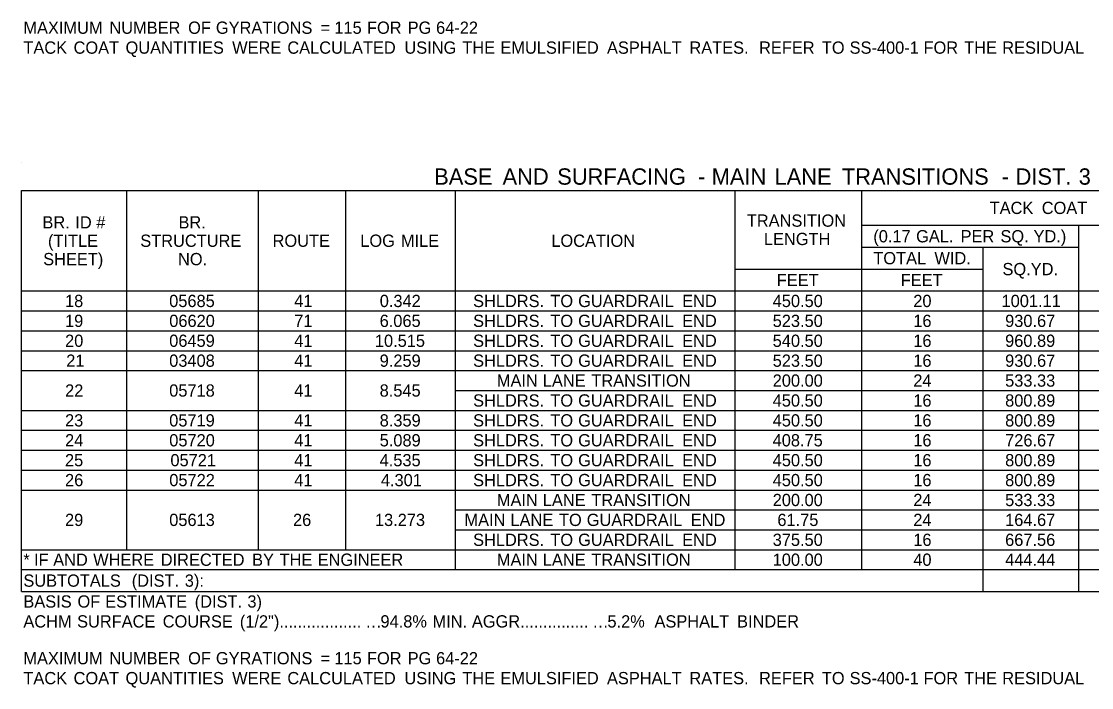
# Model space of a CAD drawing. Extents: x 544250 to 1930787, y -1948365 to 596640.
# Drawn here: x 552201 to 552725, y -1946877 to -1946551 of the extents above; entities that cross this region are included whole.
import ezdxf

# ---------------------------------------------------------------- set-up
doc = ezdxf.new("R2010")
doc.units = 0
doc.layers.add('Default', color=7, linetype='Continuous')

msp = doc.modelspace()

# ---------------------------------------------------------------- linework, layer by layer
at = {"layer": 'Default'}
for p, q in [((552201.23, -1946619.99), (552201.23, -1946619.99)), ((552201.23, -1946633.64), (552997.32, -1946633.64)), ((552201.23, -1946830.1), (552201.23, -1946633.64)), ((552252.9, -1946682.87), (552252.9, -1946633.64)), ((552317.25, -1946682.87), (552317.25, -1946633.64)), ((552360.15, -1946682.87), (552360.15, -1946633.64)), ((552413.78, -1946819.37), (552413.78, -1946633.64)), ((552550.77, -1946819.37), (552550.77, -1946633.64)), ((552612.68, -1946819.37), (552612.68, -1946633.64)), ((552612.68, -1946650.7), (552612.68, -1946633.64)), ((552612.68, -1946650.7), (552997.32, -1946650.7)), ((552718.95, -1946661.42), (552718.95, -1946650.7)), ((552718.95, -1946830.1), (552718.95, -1946650.7)), ((552612.68, -1946661.42), (552718.95, -1946661.42)), ((552672.15, -1946830.1), (552672.15, -1946661.42)), ((552550.77, -1946672.15), (552612.68, -1946672.15)), ((552550.77, -1946672.15), (552672.15, -1946672.15)), ((552672.15, -1946682.87), (552672.15, -1946672.15)), ((552201.23, -1946682.87), (552672.15, -1946682.87)), ((552252.9, -1946809.62), (552252.9, -1946682.87)), ((552317.25, -1946809.62), (552317.25, -1946682.87)), ((552360.15, -1946809.62), (552360.15, -1946682.87)), ((552672.15, -1946682.87), (552838.88, -1946682.87)), ((552672.15, -1946682.87), (552718.95, -1946682.87)), ((552201.23, -1946692.62), (552997.32, -1946692.62)), ((552201.23, -1946692.62), (552997.32, -1946692.62)), ((552201.23, -1946702.37), (552997.32, -1946702.37)), ((552201.23, -1946702.37), (552997.32, -1946702.37)), ((552201.23, -1946712.12), (552997.32, -1946712.12)), ((552201.23, -1946712.12), (552997.32, -1946712.12)), ((552201.23, -1946721.87), (552997.32, -1946721.87)), ((552413.78, -1946721.87), (552997.32, -1946721.87)), ((552413.78, -1946731.62), (552997.32, -1946731.62)), ((552413.78, -1946731.62), (552997.32, -1946731.62)), ((552201.23, -1946741.37), (552997.32, -1946741.37)), ((552201.23, -1946741.37), (552997.32, -1946741.37)), ((552201.23, -1946751.12), (552997.32, -1946751.12)), ((552201.23, -1946751.12), (552997.32, -1946751.12)), ((552201.23, -1946760.87), (552997.32, -1946760.87)), ((552201.23, -1946760.87), (552997.32, -1946760.87)), ((552201.23, -1946770.62), (552997.32, -1946770.62)), ((552201.23, -1946770.62), (552997.32, -1946770.62)), ((552201.23, -1946780.37), (552997.32, -1946780.37)), ((552201.23, -1946780.37), (552413.78, -1946780.37)), ((552413.78, -1946780.37), (552997.32, -1946780.37)), ((552413.78, -1946790.12), (552997.32, -1946790.12)), ((552413.78, -1946799.87), (552550.77, -1946799.87)), ((552413.78, -1946799.87), (552997.32, -1946799.87)), ((552672.15, -1946799.87), (552997.32, -1946799.87)), ((552201.23, -1946809.62), (552997.32, -1946809.62)), ((552413.78, -1946809.62), (552997.32, -1946809.62)), ((552201.23, -1946819.37), (552997.32, -1946819.37)), ((552201.23, -1946830.1), (552997.32, -1946830.1))]:
    msp.add_line(p, q, dxfattribs=at)

# ---------------------------------------------------------------- texts
for s, height, p in [('MAXIMUM', 6, (552202.2, -1946556.9)), (' NUMBER', 6, (552242.09, -1946556.9)), (' OF', 6, (552280.64, -1946556.9)), (' GYRATIONS', 6, (552294.23, -1946556.9)), (' =', 6, (552345.5, -1946556.9)), (' 115', 6, (552352.25, -1946556.9)), (' FOR', 6, (552368.22, -1946556.9)), (' PG', 6, (552388.14, -1946556.9)), (' 64-22', 6, (552402.05, -1946556.9)), ('TACK', 6, (552202.2, -1946566.65)), (' COAT', 6, (552224.55, -1946566.65)), (' QUANTITIES', 6, (552250, -1946566.65)), (' WERE', 6, (552302.2, -1946566.65)), (' CALCULATED', 6, (552329.23, -1946566.65)), (' USING', 6, (552386.55, -1946566.65)), (' THE', 6, (552414.9, -1946566.65)), (' EMULSIFIED', 6, (552433.55, -1946566.65)), (' ASPHALT', 6, (552485.74, -1946566.65)), (' RATES.', 6, (552526.11, -1946566.65)), ('  REFER', 6, (552557.99, -1946566.65)), (' TO', 6, (552590.95, -1946566.65)), (' SS-400-1', 6, (552604.54, -1946566.65)), (' FOR', 6, (552640.74, -1946566.65)), (' THE', 6, (552660.65, -1946566.65)), (' RESIDUAL', 6, (552679.3, -1946566.65)), ('BASE', 8, (552403.37, -1946630.81)), (' AND', 8, (552433.87, -1946630.81)), (' SURFACING', 8, (552460.64, -1946630.81)), (' -', 8, (552529.52, -1946630.81)), (' MAIN', 8, (552536.26, -1946630.81)), (' LANE', 8, (552567.03, -1946630.81)), (' TRANSITIONS', 8, (552600.01, -1946630.81)), (' -', 8, (552678.34, -1946630.81)), (' DIST.', 8, (552685.08, -1946630.81)), (' 3', 8, (552715.98, -1946630.81)), ('TACK', 6, (552675.35, -1946645.17)), (' COAT', 6, (552698.63, -1946645.17)), ('BR.', 6, (552211.54, -1946652.25)), (' ID', 6, (552225.4, -1946652.25)), (' #', 6, (552235.7, -1946652.25)), ('BR.', 6, (552278.15, -1946652.25)), ('TRANSITION', 6, (552556.44, -1946651.39)), ('(0.17', 6, (552618.38, -1946659.06)), (' GAL.', 6, (552637.1, -1946659.06)), (' PER', 6, (552658.88, -1946659.06)), (' SQ.', 6, (552678.41, -1946659.06)), (' YD.)', 6, (552694.6, -1946659.06)), ('(TITLE', 6, (552214.24, -1946661.25)), ('STRUCTURE', 6, (552259.44, -1946661.25)), ('ROUTE', 6, (552324.24, -1946661.25)), ('LOG', 6, (552367.17, -1946661.25)), (' MILE', 6, (552384.83, -1946661.25)), ('LOCATION', 6, (552460.72, -1946661.25)), ('LENGTH', 6, (552564.81, -1946660.39)), ('SHEET)', 6, (552211.91, -1946670.25)), ('NO.', 6, (552277.92, -1946670.25)), ('TOTAL', 6, (552618.39, -1946669.79)), (' WID.', 6, (552646.08, -1946669.79)), ('SQ.YD.', 6, (552681.63, -1946675.15)), ('FEET', 6, (552571.1, -1946680.51)), ('FEET', 6, (552631.79, -1946680.51)), ('18', 6, (552222.59, -1946690.75)), ('05685', 6, (552273.6, -1946690.75)), ('41', 6, (552334.82, -1946690.75)), ('0.342', 6, (552376.7, -1946690.75)), ('SHLDRS.', 6, (552422.41, -1946690.75)), (' TO', 6, (552458.01, -1946690.75)), (' GUARDRAIL', 6, (552471.61, -1946690.75)), (' END', 6, (552522.56, -1946690.75)), ('450.50', 6, (552569.11, -1946690.75)), ('20', 6, (552637.96, -1946690.75)), ('1001.11', 6, (552681.18, -1946690.75)), ('19', 6, (552222.59, -1946700.5)), ('06620', 6, (552273.63, -1946700.5)), ('71', 6, (552334.82, -1946700.5)), ('6.065', 6, (552376.65, -1946700.5)), ('SHLDRS.', 6, (552422.41, -1946700.5)), (' TO', 6, (552458.01, -1946700.5)), (' GUARDRAIL', 6, (552471.61, -1946700.5)), (' END', 6, (552522.56, -1946700.5)), ('523.50', 6, (552569.11, -1946700.5)), ('16', 6, (552637.95, -1946700.5)), ('930.67', 6, (552682.93, -1946700.5)), ('20', 6, (552222.61, -1946710.25)), ('06459', 6, (552273.61, -1946710.25)), ('41', 6, (552334.82, -1946710.25)), ('10.515', 6, (552374.32, -1946710.25)), ('SHLDRS.', 6, (552422.41, -1946710.25)), (' TO', 6, (552458.01, -1946710.25)), (' GUARDRAIL', 6, (552471.61, -1946710.25)), (' END', 6, (552522.56, -1946710.25)), ('540.50', 6, (552569.11, -1946710.25)), ('16', 6, (552637.95, -1946710.25)), ('960.89', 6, (552682.93, -1946710.25)), ('21', 6, (552223.18, -1946720)), ('03408', 6, (552273.61, -1946720)), ('41', 6, (552334.82, -1946720)), ('9.259', 6, (552376.67, -1946720)), ('SHLDRS.', 6, (552422.41, -1946720)), (' TO', 6, (552458.01, -1946720)), (' GUARDRAIL', 6, (552471.61, -1946720)), (' END', 6, (552522.56, -1946720)), ('523.50', 6, (552569.11, -1946720)), ('16', 6, (552637.95, -1946720)), ('930.67', 6, (552682.93, -1946720)), ('MAIN', 6, (552434.04, -1946729.75)), (' LANE', 6, (552454.31, -1946729.75)), (' TRANSITION', 6, (552478.09, -1946729.75)), ('200.00', 6, (552569.11, -1946729.75)), ('24', 6, (552637.96, -1946729.75)), ('533.33', 6, (552682.93, -1946729.75)), ('22', 6, (552222.63, -1946734.62)), ('05718', 6, (552273.61, -1946734.62)), ('41', 6, (552334.82, -1946734.62)), ('8.545', 6, (552376.65, -1946734.62)), ('SHLDRS.', 6, (552422.41, -1946739.5)), (' TO', 6, (552458.01, -1946739.5)), (' GUARDRAIL', 6, (552471.61, -1946739.5)), (' END', 6, (552522.56, -1946739.5)), ('450.50', 6, (552569.11, -1946739.5)), ('16', 6, (552637.95, -1946739.5)), ('800.89', 6, (552682.93, -1946739.5)), ('23', 6, (552222.6, -1946749.25)), ('05719', 6, (552273.61, -1946749.25)), ('41', 6, (552334.82, -1946749.25)), ('8.359', 6, (552376.67, -1946749.25)), ('SHLDRS.', 6, (552422.41, -1946749.25)), (' TO', 6, (552458.01, -1946749.25)), (' GUARDRAIL', 6, (552471.61, -1946749.25)), (' END', 6, (552522.56, -1946749.25)), ('450.50', 6, (552569.11, -1946749.25)), ('16', 6, (552637.95, -1946749.25)), ('800.89', 6, (552682.93, -1946749.25)), ('24', 6, (552222.61, -1946759)), ('05720', 6, (552273.63, -1946759)), ('41', 6, (552334.82, -1946759)), ('5.089', 6, (552376.67, -1946759)), ('SHLDRS.', 6, (552422.41, -1946759)), (' TO', 6, (552458.01, -1946759)), (' GUARDRAIL', 6, (552471.61, -1946759)), (' END', 6, (552522.56, -1946759)), ('408.75', 6, (552569.08, -1946759)), ('16', 6, (552637.95, -1946759)), ('726.67', 6, (552682.93, -1946759)), ('25', 6, (552222.57, -1946768.75)), ('05721', 6, (552274.2, -1946768.75)), ('41', 6, (552334.82, -1946768.75)), ('4.535', 6, (552376.65, -1946768.75)), ('SHLDRS.', 6, (552422.41, -1946768.75)), (' TO', 6, (552458.01, -1946768.75)), (' GUARDRAIL', 6, (552471.61, -1946768.75)), (' END', 6, (552522.56, -1946768.75)), ('450.50', 6, (552569.11, -1946768.75)), ('16', 6, (552637.95, -1946768.75)), ('800.89', 6, (552682.93, -1946768.75)), ('26', 6, (552222.6, -1946778.5)), ('05722', 6, (552273.65, -1946778.5)), ('41', 6, (552334.82, -1946778.5)), ('4.301', 6, (552377.25, -1946778.5)), ('SHLDRS.', 6, (552422.41, -1946778.5)), (' TO', 6, (552458.01, -1946778.5)), (' GUARDRAIL', 6, (552471.61, -1946778.5)), (' END', 6, (552522.56, -1946778.5)), ('450.50', 6, (552569.11, -1946778.5)), ('16', 6, (552637.95, -1946778.5)), ('800.89', 6, (552682.93, -1946778.5)), ('MAIN', 6, (552434.04, -1946788.25)), (' LANE', 6, (552454.31, -1946788.25)), (' TRANSITION', 6, (552478.09, -1946788.25)), ('200.00', 6, (552569.11, -1946788.25)), ('24', 6, (552637.96, -1946788.25)), ('533.33', 6, (552682.93, -1946788.25)), ('29', 6, (552222.59, -1946798)), ('05613', 6, (552273.62, -1946798)), ('26', 6, (552334.23, -1946798)), ('13.273', 6, (552374.34, -1946798)), ('MAIN', 6, (552418.18, -1946798)), (' LANE', 6, (552438.46, -1946798)), (' TO', 6, (552462.24, -1946798)), (' GUARDRAIL', 6, (552475.83, -1946798)), (' END', 6, (552526.78, -1946798)), ('61.75', 6, (552571.41, -1946798)), ('24', 6, (552637.96, -1946798)), ('164.67', 6, (552682.93, -1946798)), ('SHLDRS.', 6, (552422.41, -1946807.75)), (' TO', 6, (552458.01, -1946807.75)), (' GUARDRAIL', 6, (552471.61, -1946807.75)), (' END', 6, (552522.56, -1946807.75)), ('375.50', 6, (552569.11, -1946807.75)), ('16', 6, (552637.95, -1946807.75)), ('667.56', 6, (552682.93, -1946807.75)), ('*', 6, (552202.2, -1946817.5)), (' IF', 6, (552205.17, -1946817.5)), (' AND', 6, (552214.57, -1946817.5)), (' WHERE', 6, (552234.15, -1946817.5)), (' DIRECTED', 6, (552267.24, -1946817.5)), (' BY', 6, (552311.97, -1946817.5)), (' THE', 6, (552325.42, -1946817.5)), (' ENGINEER', 6, (552344.07, -1946817.5)), ('MAIN', 6, (552434.04, -1946817.5)), (' LANE', 6, (552454.31, -1946817.5)), (' TRANSITION', 6, (552478.09, -1946817.5)), ('100.00', 6, (552569.11, -1946817.5)), ('40', 6, (552637.96, -1946817.5)), ('444.44', 6, (552682.94, -1946817.5)), ('SUBTOTALS', 6, (552202.2, -1946827.74)), (' (DIST.', 6, (552253.03, -1946827.74)), (' 3):', 6, (552279, -1946827.74)), ('BASIS', 6, (552202.2, -1946837.97)), (' OF', 6, (552226.47, -1946837.97)), (' ESTIMATE', 6, (552240.05, -1946837.97)), (' (DIST.', 6, (552283.86, -1946837.97)), (' 3)', 6, (552309.67, -1946837.97)), ('ACHM', 6, (552202.2, -1946847.72)), (' SURFACE', 6, (552226.26, -1946847.72)), (' COURSE', 6, (552268.2, -1946847.72)), (' (1/2")..................', 6, (552305.96, -1946847.72)), ('94.8%', 6, (552377.06, -1946847.72)), (' MIN.', 6, (552400.3, -1946847.72)), (' AGGR...............', 6, (552419.59, -1946847.72)), ('5.2%', 6, (552488.19, -1946847.72)), ('  ASPHALT', 6, (552506.77, -1946847.72)), (' BINDER', 6, (552549.46, -1946847.72)), ('…', 6, (552369.66, -1946847.72)), ('…', 6, (552480.79, -1946847.72)), ('MAXIMUM', 6, (552202.2, -1946865.76)), (' NUMBER', 6, (552242.09, -1946865.76)), (' OF', 6, (552280.64, -1946865.76)), (' GYRATIONS', 6, (552294.23, -1946865.76)), (' =', 6, (552345.5, -1946865.76)), (' 115', 6, (552352.25, -1946865.76)), (' FOR', 6, (552368.22, -1946865.76)), (' PG', 6, (552388.14, -1946865.76)), (' 64-22', 6, (552402.05, -1946865.76)), ('TACK', 6, (552202.2, -1946875.51)), (' COAT', 6, (552224.55, -1946875.51)), (' QUANTITIES', 6, (552250, -1946875.51)), (' WERE', 6, (552302.2, -1946875.51)), (' CALCULATED', 6, (552329.23, -1946875.51)), (' USING', 6, (552386.55, -1946875.51)), (' THE', 6, (552414.9, -1946875.51)), (' EMULSIFIED', 6, (552433.55, -1946875.51)), (' ASPHALT', 6, (552485.74, -1946875.51)), (' RATES.', 6, (552526.11, -1946875.51)), ('  REFER', 6, (552557.99, -1946875.51)), (' TO', 6, (552590.95, -1946875.51)), (' SS-400-1', 6, (552604.54, -1946875.51)), (' FOR', 6, (552640.74, -1946875.51)), (' THE', 6, (552660.65, -1946875.51)), (' RESIDUAL', 6, (552679.3, -1946875.51))]:
    msp.add_text(s, height=height, dxfattribs=at).set_placement(p)

doc.saveas('drawing.dxf')
